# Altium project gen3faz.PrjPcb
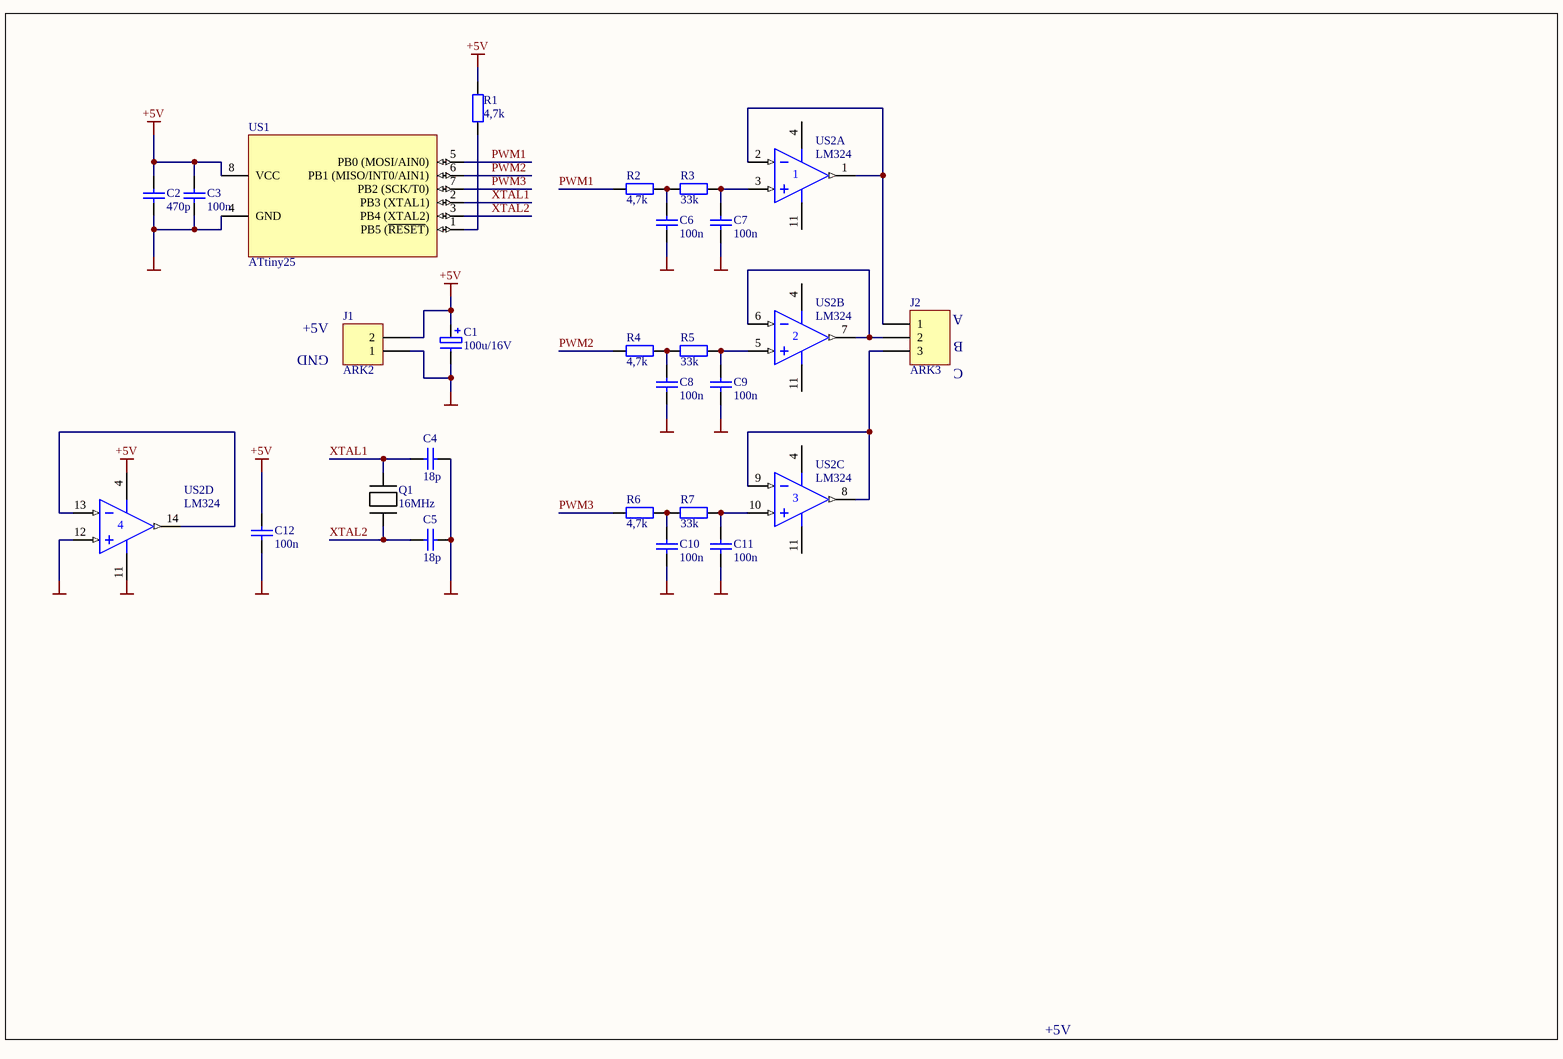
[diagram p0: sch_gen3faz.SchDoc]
1 sheet, 24 parts. Net scope: global (net labels, ports and power ports of the same name join across sheets).
Board file: pcb_gen3faz.PcbDoc

## Sheet sch_gen3faz.SchDoc
size A4

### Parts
C1  100u/16V  [2,5/5mm elektrolit]
C2  470p  [MELF-1206]
C3  100n  [MELF-1206]
C4  18p  [MELF-1206]
C5  18p  [MELF-1206]
C6  100n  [MELF-1206]
C7  100n  [MELF-1206]
C8  100n  [MELF-1206]
C9  100n  [MELF-1206]
C10  100n  [MELF-1206]
C11  100n  [MELF-1206]
C12  100n  [MELF-1206]
J1  ARK2  [ARK2 5mm]
J2  ARK3  [ARK3 5mm]
Q1  16MHz  [kwarc 5mm]
R1  4,7k  [MELF-1206]
R2  4,7k  [MELF-1206]
R3  33k  [MELF-1206]
R4  4,7k  [MELF-1206]
R5  33k  [MELF-1206]
R6  4,7k  [MELF-1206]
R7  33k  [MELF-1206]
US1  ATtiny25  [8P3]
US2  LM324  [N014]  (parts A,B,C,D of 4)

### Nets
+5V: C1.1 C2.2 C3.2 C12.2 J1.2 R1.2 US1.8(VCC) US2.4(V+)
GND: C1.2 C2.1 C3.1 C4.1 C5.1 C6.1 C7.1 C8.1 C9.1 C10.1 C11.1 C12.1 J1.1 US1.4(GND) US2.11(V-) US2.12(IN+)
PWM1: R2.2 US1.5(PB0_(MOSI/AIN0))
PWM2: R4.2 US1.6(PB1_(MISO/INT0/AIN1))
PWM3: R6.2 US1.7(PB2_(SCK/T0))
XTAL1: C4.2 Q1.2 US1.2(PB3_(XTAL1))
XTAL2: C5.2 Q1.1 US1.3(PB4_(XTAL2))
NetC6_2: C6.2 R2.1 R3.2
NetC7_2: C7.2 R3.1 US2.3(IN+)
NetC8_2: C8.2 R4.1 R5.2
NetC9_2: C9.2 R5.1 US2.5(IN+)
NetC10_2: C10.2 R6.1 R7.2
NetC11_2: C11.2 R7.1 US2.10(IN+)
NetJ2_1: J2.1 US2.1(OUT) US2.2(IN-)
NetJ2_2: J2.2 US2.6(IN-) US2.7(OUT)
NetJ2_3: J2.3 US2.8(OUT) US2.9(IN-)
NetR1_1: R1.1 US1.1(PB5_(~{RESET}))
NetUS2_13: US2.13(IN-) US2.14(OUT)

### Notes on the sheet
- (near J2) A
- +5V
- GND
- (near J2) B
- (near J2) C

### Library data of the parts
C1 = kond biegunowy: Polarized Capacitor
C2 C4 C5 = kondensator: Value: 100n
C3 C6-C12 = kondensator
Q1 = kwarc
R1-R7 = rezystor
US1 = ATtiny12V-1PI: 8-Bit AVR Microcontroller with 1K Byte of Flash Memory
US2 = LM324AN: Quadruple Operational Amplifier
